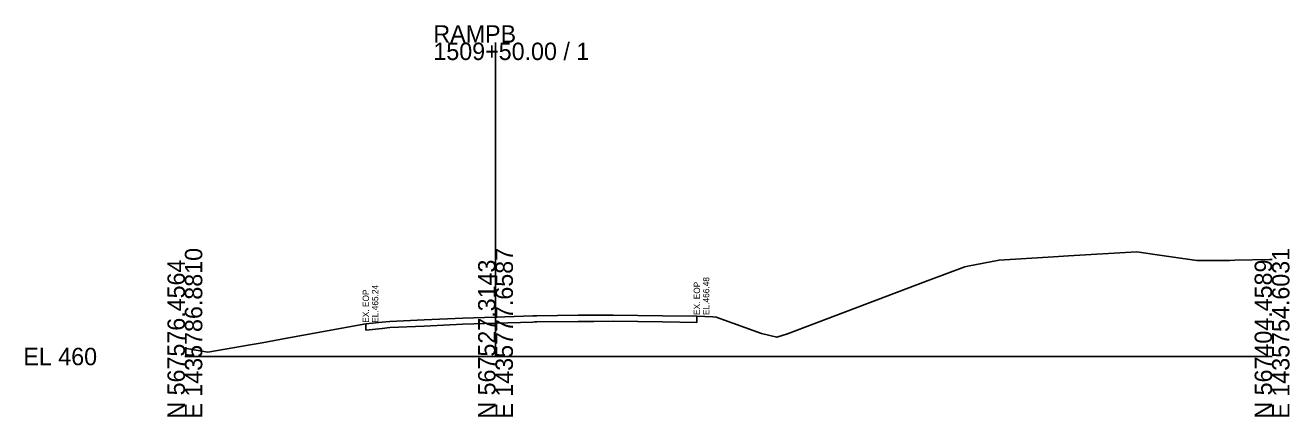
# Model space of a CAD drawing. Extents: x 1431908 to 1449087, y 567604 to 577825.
# Drawn here: x 1440484.4 to 1440688, y 576048.6 to 576111.7 of the extents above; entities that cross this region are included whole.
import ezdxf

# ---------------------------------------------------------------- set-up
doc = ezdxf.new("R2010")
doc.units = 0
for name, color, linetype in [('DESIGN - SHEET - Light Grid', 7, 'Continuous'), ('SURVEY - GROUND - Existing Pavement Layer', 7, 'Continuous'), ('SURVEY - GROUND - Existing Pavement Text', 7, 'Continuous'), ('SURVEY - GROUND - Top of Ground', 7, 'Continuous')]:
    doc.layers.add(name, color=color, linetype=linetype)

msp = doc.modelspace()

# ---------------------------------------------------------------- linework, layer by layer
at = {"layer": 'DESIGN - SHEET - Light Grid'}
for p, q in [((1440560.12, 576058.33), (1440560.12, 576108.87)), ((1440510.12, 576058.33), (1440560.12, 576058.33)), ((1440560.12, 576058.33), (1440685.12, 576058.33))]:
    msp.add_line(p, q, dxfattribs=at)
at = {"layer": 'SURVEY - GROUND - Existing Pavement Layer'}
for p, q in [((1440592.53, 576064.82), (1440592.53, 576063.82)), ((1440539.24, 576062.57), (1440539.24, 576063.57)), ((1440539.24, 576062.57), (1440541.85, 576062.85)), ((1440541.85, 576062.85), (1440543.09, 576062.99)), ((1440543.09, 576062.99), (1440548.65, 576063.24)), ((1440548.65, 576063.24), (1440554.88, 576063.52)), ((1440554.88, 576063.52), (1440560.12, 576063.69)), ((1440560.12, 576063.69), (1440566.12, 576063.88)), ((1440566.12, 576063.88), (1440566.44, 576063.89)), ((1440566.44, 576063.89), (1440566.79, 576063.89)), ((1440566.79, 576063.89), (1440573.45, 576063.97)), ((1440573.45, 576063.97), (1440575.97, 576063.99)), ((1440575.97, 576063.99), (1440579.07, 576064.01)), ((1440579.07, 576064.01), (1440586.99, 576063.89)), ((1440586.99, 576063.89), (1440592.53, 576063.82))]:
    msp.add_line(p, q, dxfattribs=at)
at = {"layer": 'SURVEY - GROUND - Top of Ground'}
msp.add_lwpolyline([(1440510.12, 576059.66), (1440511.62, 576059.41), (1440513.8, 576059.05), (1440520.65, 576060.23), (1440522.56, 576060.56), (1440526.53, 576061.27), (1440539.24, 576063.57), (1440541.85, 576063.85), (1440543.09, 576063.99), (1440548.65, 576064.24), (1440554.88, 576064.52), (1440560.12, 576064.69), (1440566.12, 576064.88), (1440566.44, 576064.89), (1440566.79, 576064.89), (1440573.45, 576064.97), (1440575.97, 576064.99), (1440579.07, 576065.01), (1440586.99, 576064.89), (1440592.53, 576064.82), (1440595.08, 576064.72), (1440595.63, 576064.68), (1440602.93, 576062.03), (1440605.38, 576061.43), (1440607.13, 576061.98), (1440629.32, 576070.43), (1440635.67, 576072.78), (1440636.16, 576072.88), (1440641.19, 576073.85), (1440649.92, 576074.39), (1440652.34, 576074.53), (1440663.37, 576075.18), (1440666.65, 576074.7), (1440673.02, 576073.81), (1440677.61, 576073.81), (1440678.33, 576073.81), (1440679.11, 576073.83), (1440684.78, 576073.96), (1440685.12, 576073.95)], dxfattribs=at)

# ---------------------------------------------------------------- texts
at = {"layer": 'DESIGN - SHEET - Light Grid'}
for s, p in [('RAMPB', (1440550.12, 576108.87)), ('1509+50.00 / 1', (1440550.12, 576106.07)), ('EL 460', (1440484.12, 576056.93))]:
    msp.add_text(s, height=2.8, dxfattribs=at).set_placement(p)
for s, p in [('E 1435786.8810', (1440512.92, 576048.33)), ('E 1435777.6587', (1440562.92, 576048.33)), ('E 1435754.6031', (1440687.92, 576048.33)), ('N 567576.4564', (1440510.12, 576048.33)), ('N 567527.3143', (1440560.12, 576048.33)), ('N 567404.4589', (1440685.12, 576048.33))]:
    msp.add_text(s, height=2.8, rotation=90, dxfattribs=at).set_placement(p)
at = {"layer": 'SURVEY - GROUND - Existing Pavement Text'}
for s, p in [('EL.466.48', (1440594.53, 576065.02)), ('EX. EOP', (1440539.74, 576063.77)), ('EL.465.24', (1440541.24, 576063.77)), ('EX. EOP', (1440593.03, 576065.02))]:
    msp.add_text(s, height=1, rotation=90, dxfattribs=at).set_placement(p)

doc.saveas('drawing.dxf')
